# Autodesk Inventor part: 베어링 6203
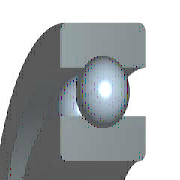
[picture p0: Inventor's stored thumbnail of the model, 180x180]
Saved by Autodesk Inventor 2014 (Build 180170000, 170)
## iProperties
IsCustomPart: 0
Company: 한국ATC센터
Created: 2014-08
Part Number: 베어링 6203
Material: 강, 연강
Description: 깊은 그루브 볼 베어링
Document SubType Name: Modeling
Standard: KS B 2023
Designer: KYOUNG IL JANG
Standards Organization: KS
Language: ko-KR
Size Designation: 6203 - 17 x 40 x 12
Categories: <MemberInstance><Categories><Category DisplayName="샤프트 부품" InternalName="7f7aeb1f-a693-4053-b835-cee3144e0d98" Mnemonic="SHFT"><Category DisplayName="베어링" Inter
Density: 7.86 g/cm^3
Appearance: 크롬 - 광택
Mass: 58.8203 g
Surface Area: 64.3582 cm^2
Volume: 7.4835 cm^3
Author: KYOUNG IL JANG
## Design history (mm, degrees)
sketch "스케치" dims "d0" = 5.98 (= -0.26 x WD + 0.26 x BD)
  geometry: L1 (3.01, 14.25)-(8.99, 14.25); L2 (6, 14.25)-(6, 11.26); L3 (6, 14.25)-(6, 17.24); L4 (3.778, 12.249)-(0, 12.249); L5 (0, 8.5)-(12, 8.5); L6 (3.778, 16.251)-(0, 16.251); L7 (0, 20)-(12, 20); L8 (12, 8.5)-(12, 12.249); L9 (8.222, 12.249)-(12, 12.249); L10 (8.222, 16.251)-(12, 16.251); L11 (12, 20)-(12, 16.251); L12 (-1.4, 0)-(8.4, 0) reference; L13 (0, -0.3)-(0, 5.3) reference
  constraints: 22 end point, 4 point on line, 2 collinear, 2 perpendicular, 2 symmetric about line, 1 midpoint, 1 parallel, 14 other
  dimensions: "d9" = 17 diameter of L5 L12 (= WD); "d11" = 40 diameter of L7 L12 (= BD); "d12" = 12 distance between parallel lines of L8 L13 (= KB); "d13" = 24.498 diameter of L9 L12 (= 0.326 x BD + 0.674 x WD)
revolve "본체" stored, may be unused: angle "d6" = 90 deg
revolve "볼" stored, may be unused: angle "d7" = 90 deg
pattern_circular "IDS_ARRAYBALL[SIMPL:T]" dims angle "d3" = 360 deg
body "Solid1"
fillet "모깎기1" dims "d1" = 0.6 (= KRS)
other parameters: "WD" = 17 [user parameter; used in 5 equation terms], "BD" = 40 [user parameter; used in 5 equation terms], "KB" = 12 [user parameter; used in 1 equation term], "KRS" = 0.6 [user parameter; used in 1 equation term], "d4" = 0, "d5" = 0, "d8" = 0, "d14" = 0, "d15" = 0, "BBA" = 0 [user parameter], "BC0" = 4750000 [user parameter], "BC" = 9560000 [user parameter], "WR" = 8.5 (= 0.5 x WD) [user parameter]
